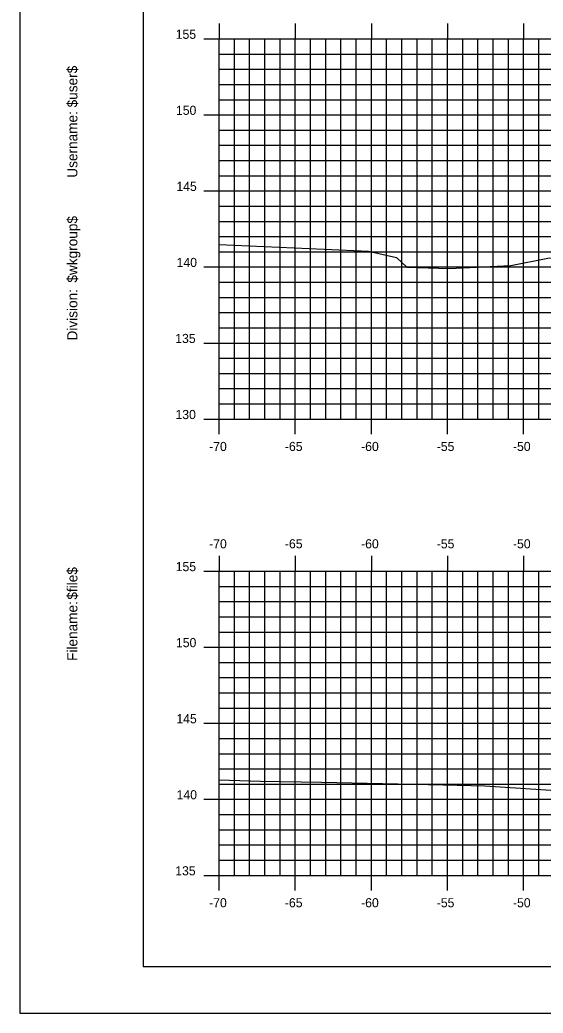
# Model space of a CAD drawing. Extents: x 851195 to 851367, y 365876 to 365986.
# Drawn here: x 851195 to 851229.4, y 365875.8 to 365941.1 of the extents above; entities that cross this region are included whole.
import ezdxf

# ---------------------------------------------------------------- set-up
doc = ezdxf.new("R2010")
doc.units = 0
for name, color, linetype in [('BORDER', 7, 'Continuous'), ('H_V ANNOTATION', 7, 'Continuous'), ('MAJOR', 7, 'Continuous'), ('MINOR', 7, 'Continuous'), ('PLOT BOUNDARY', 7, 'Continuous'), ('S_Roadway_Centerline', 7, 'Continuous')]:
    doc.layers.add(name, color=color, linetype=linetype)

msp = doc.modelspace()

# ---------------------------------------------------------------- linework, layer by layer
at = {"layer": 'BORDER'}
msp.add_lwpolyline([(851203.142, 365878.833), (851363.142, 365878.833), (851363.142, 365983.833), (851203.142, 365983.833)], close=True, dxfattribs=at)
at = {"layer": 'MAJOR'}
for p, q in [((851208.142, 365940.835), (851208.142, 365939.833)), ((851213.142, 365940.835), (851213.142, 365939.833)), ((851218.142, 365940.835), (851218.142, 365939.833)), ((851223.142, 365940.835), (851223.142, 365939.833)), ((851228.142, 365940.835), (851228.142, 365939.833)), ((851207.14, 365939.833), (851208.142, 365939.833)), ((851208.142, 365939.833), (851348.142, 365939.833)), ((851208.142, 365914.833), (851208.142, 365939.833)), ((851208.142, 365914.833), (851208.142, 365939.833)), ((851208.142, 365939.833), (851348.142, 365939.833)), ((851213.142, 365914.833), (851213.142, 365939.833)), ((851218.142, 365914.833), (851218.142, 365939.833)), ((851223.142, 365914.833), (851223.142, 365939.833)), ((851228.142, 365914.833), (851228.142, 365939.833)), ((851207.14, 365934.833), (851208.142, 365934.833)), ((851208.142, 365934.833), (851348.142, 365934.833)), ((851207.14, 365929.833), (851208.142, 365929.833)), ((851208.142, 365929.833), (851348.142, 365929.833)), ((851207.14, 365924.833), (851208.142, 365924.833)), ((851208.142, 365924.833), (851348.142, 365924.833)), ((851207.14, 365919.833), (851208.142, 365919.833)), ((851208.142, 365919.833), (851348.142, 365919.833)), ((851207.14, 365914.833), (851208.142, 365914.833)), ((851208.142, 365914.833), (851348.142, 365914.833)), ((851208.142, 365914.833), (851348.142, 365914.833)), ((851208.142, 365913.831), (851208.142, 365914.833)), ((851213.142, 365913.831), (851213.142, 365914.833)), ((851218.142, 365913.831), (851218.142, 365914.833)), ((851223.142, 365913.831), (851223.142, 365914.833)), ((851228.142, 365913.831), (851228.142, 365914.833)), ((851208.142, 365905.835), (851208.142, 365904.833)), ((851213.142, 365905.835), (851213.142, 365904.833)), ((851218.142, 365905.835), (851218.142, 365904.833)), ((851223.142, 365905.835), (851223.142, 365904.833)), ((851228.142, 365905.835), (851228.142, 365904.833)), ((851207.14, 365904.833), (851208.142, 365904.833)), ((851208.142, 365904.833), (851348.142, 365904.833)), ((851208.142, 365884.833), (851208.142, 365904.833)), ((851208.142, 365884.833), (851208.142, 365904.833)), ((851208.142, 365904.833), (851348.142, 365904.833)), ((851213.142, 365884.833), (851213.142, 365904.833)), ((851218.142, 365884.833), (851218.142, 365904.833)), ((851223.142, 365884.833), (851223.142, 365904.833)), ((851228.142, 365884.833), (851228.142, 365904.833)), ((851207.14, 365899.833), (851208.142, 365899.833)), ((851208.142, 365899.833), (851348.142, 365899.833)), ((851207.14, 365894.833), (851208.142, 365894.833)), ((851208.142, 365894.833), (851348.142, 365894.833)), ((851207.14, 365889.833), (851208.142, 365889.833)), ((851208.142, 365889.833), (851348.142, 365889.833)), ((851207.14, 365884.833), (851208.142, 365884.833)), ((851208.142, 365884.833), (851348.142, 365884.833)), ((851208.142, 365884.833), (851348.142, 365884.833)), ((851208.142, 365883.831), (851208.142, 365884.833)), ((851213.142, 365883.831), (851213.142, 365884.833)), ((851218.142, 365883.831), (851218.142, 365884.833)), ((851223.142, 365883.831), (851223.142, 365884.833)), ((851228.142, 365883.831), (851228.142, 365884.833))]:
    msp.add_line(p, q, dxfattribs=at)
at = {"layer": 'MINOR'}
for p, q in [((851209.142, 365914.833), (851209.142, 365939.833)), ((851210.142, 365914.833), (851210.142, 365939.833)), ((851211.142, 365914.833), (851211.142, 365939.833)), ((851212.142, 365914.833), (851212.142, 365939.833)), ((851214.142, 365914.833), (851214.142, 365939.833)), ((851215.142, 365914.833), (851215.142, 365939.833)), ((851216.142, 365914.833), (851216.142, 365939.833)), ((851217.142, 365914.833), (851217.142, 365939.833)), ((851219.142, 365914.833), (851219.142, 365939.833)), ((851220.142, 365914.833), (851220.142, 365939.833)), ((851221.142, 365914.833), (851221.142, 365939.833)), ((851222.142, 365914.833), (851222.142, 365939.833)), ((851224.142, 365914.833), (851224.142, 365939.833)), ((851225.142, 365914.833), (851225.142, 365939.833)), ((851226.142, 365914.833), (851226.142, 365939.833)), ((851227.142, 365914.833), (851227.142, 365939.833)), ((851229.142, 365914.833), (851229.142, 365939.833)), ((851208.142, 365938.833), (851348.142, 365938.833)), ((851208.142, 365938.833), (851209.144, 365938.833)), ((851208.142, 365937.833), (851348.142, 365937.833)), ((851208.142, 365937.833), (851209.144, 365937.833)), ((851208.142, 365936.833), (851348.142, 365936.833)), ((851208.142, 365936.833), (851209.144, 365936.833)), ((851208.142, 365935.833), (851348.142, 365935.833)), ((851208.142, 365935.833), (851209.144, 365935.833)), ((851208.142, 365933.833), (851348.142, 365933.833)), ((851208.142, 365933.833), (851209.144, 365933.833)), ((851208.142, 365932.833), (851348.142, 365932.833)), ((851208.142, 365932.833), (851209.144, 365932.833)), ((851208.142, 365931.833), (851348.142, 365931.833)), ((851208.142, 365931.833), (851209.144, 365931.833)), ((851208.142, 365930.833), (851348.142, 365930.833)), ((851208.142, 365930.833), (851209.144, 365930.833)), ((851208.142, 365928.833), (851348.142, 365928.833)), ((851208.142, 365928.833), (851209.144, 365928.833)), ((851208.142, 365927.833), (851348.142, 365927.833)), ((851208.142, 365927.833), (851209.144, 365927.833)), ((851208.142, 365926.833), (851348.142, 365926.833)), ((851208.142, 365926.833), (851209.144, 365926.833)), ((851208.142, 365925.833), (851348.142, 365925.833)), ((851208.142, 365925.833), (851209.144, 365925.833)), ((851208.142, 365923.833), (851348.142, 365923.833)), ((851208.142, 365923.833), (851209.144, 365923.833)), ((851208.142, 365922.833), (851348.142, 365922.833)), ((851208.142, 365922.833), (851209.144, 365922.833)), ((851208.142, 365921.833), (851348.142, 365921.833)), ((851208.142, 365921.833), (851209.144, 365921.833)), ((851208.142, 365920.833), (851348.142, 365920.833)), ((851208.142, 365920.833), (851209.144, 365920.833)), ((851208.142, 365918.833), (851348.142, 365918.833)), ((851208.142, 365918.833), (851209.144, 365918.833)), ((851208.142, 365917.833), (851348.142, 365917.833)), ((851208.142, 365917.833), (851209.144, 365917.833)), ((851208.142, 365916.833), (851348.142, 365916.833)), ((851208.142, 365916.833), (851209.144, 365916.833)), ((851208.142, 365915.833), (851348.142, 365915.833)), ((851208.142, 365915.833), (851209.144, 365915.833)), ((851209.142, 365884.833), (851209.142, 365904.833)), ((851210.142, 365884.833), (851210.142, 365904.833)), ((851211.142, 365884.833), (851211.142, 365904.833)), ((851212.142, 365884.833), (851212.142, 365904.833)), ((851214.142, 365884.833), (851214.142, 365904.833)), ((851215.142, 365884.833), (851215.142, 365904.833)), ((851216.142, 365884.833), (851216.142, 365904.833)), ((851217.142, 365884.833), (851217.142, 365904.833)), ((851219.142, 365884.833), (851219.142, 365904.833)), ((851220.142, 365884.833), (851220.142, 365904.833)), ((851221.142, 365884.833), (851221.142, 365904.833)), ((851222.142, 365884.833), (851222.142, 365904.833)), ((851224.142, 365884.833), (851224.142, 365904.833)), ((851225.142, 365884.833), (851225.142, 365904.833)), ((851226.142, 365884.833), (851226.142, 365904.833)), ((851227.142, 365884.833), (851227.142, 365904.833)), ((851229.142, 365884.833), (851229.142, 365904.833)), ((851208.142, 365903.833), (851348.142, 365903.833)), ((851208.142, 365903.833), (851209.144, 365903.833)), ((851208.142, 365902.833), (851348.142, 365902.833)), ((851208.142, 365902.833), (851209.144, 365902.833)), ((851208.142, 365901.833), (851348.142, 365901.833)), ((851208.142, 365901.833), (851209.144, 365901.833)), ((851208.142, 365900.833), (851348.142, 365900.833)), ((851208.142, 365900.833), (851209.144, 365900.833)), ((851208.142, 365898.833), (851348.142, 365898.833)), ((851208.142, 365898.833), (851209.144, 365898.833)), ((851208.142, 365897.833), (851348.142, 365897.833)), ((851208.142, 365897.833), (851209.144, 365897.833)), ((851208.142, 365896.833), (851348.142, 365896.833)), ((851208.142, 365896.833), (851209.144, 365896.833)), ((851208.142, 365895.833), (851348.142, 365895.833)), ((851208.142, 365895.833), (851209.144, 365895.833)), ((851208.142, 365893.833), (851348.142, 365893.833)), ((851208.142, 365893.833), (851209.144, 365893.833)), ((851208.142, 365892.833), (851348.142, 365892.833)), ((851208.142, 365892.833), (851209.144, 365892.833)), ((851208.142, 365891.833), (851348.142, 365891.833)), ((851208.142, 365891.833), (851209.144, 365891.833)), ((851208.142, 365890.833), (851348.142, 365890.833)), ((851208.142, 365890.833), (851209.144, 365890.833)), ((851208.142, 365888.833), (851348.142, 365888.833)), ((851208.142, 365888.833), (851209.144, 365888.833)), ((851208.142, 365887.833), (851348.142, 365887.833)), ((851208.142, 365887.833), (851209.144, 365887.833)), ((851208.142, 365886.833), (851348.142, 365886.833)), ((851208.142, 365886.833), (851209.144, 365886.833)), ((851208.142, 365885.833), (851348.142, 365885.833)), ((851208.142, 365885.833), (851209.144, 365885.833))]:
    msp.add_line(p, q, dxfattribs=at)
at = {"layer": 'PLOT BOUNDARY'}
msp.add_lwpolyline([(851195.049, 365875.774), (851365.049, 365875.774), (851365.049, 365985.774), (851195.049, 365985.774)], close=True, dxfattribs=at)
at = {"layer": 'S_Roadway_Centerline'}
for points in [[(851208.142, 365926.314), (851215.041, 365926.007), (851217.958, 365925.881), (851219.79, 365925.455), (851220.465, 365924.815), (851223.262, 365924.724), (851227.308, 365924.921), (851229.726, 365925.418), (851232.295, 365925.52), (851235.754, 365925.302), (851242.416, 365925.714), (851245.078, 365925.751), (851253.803, 365925.182), (851257.459, 365925.158), (851270.86, 365925.023), (851276.825, 365924.935), (851280.32, 365925.09), (851285.065, 365924.889), (851286.257, 365924.7), (851295.049, 365925.23), (851296.011, 365925.262), (851296.222, 365925.276), (851305.027, 365925.458)], [(851208.142, 365891.121), (851210.866, 365891.029), (851214.856, 365890.97), (851222.885, 365890.78), (851225.59, 365890.713), (851230.612, 365890.393)]]:
    msp.add_lwpolyline(points, dxfattribs=at)

# ---------------------------------------------------------------- texts
at = {"layer": 'BORDER'}
for s, p in [('$user$', (851198.827, 365935.325)), ('Username:', (851198.827, 365930.701)), ('$wkgroup$', (851198.827, 365923.803)), ('Division:', (851198.827, 365919.999)), ('$file$', (851198.827, 365902.959)), ('Filename:', (851198.827, 365898.932))]:
    msp.add_text(s, height=0.6696, rotation=90, dxfattribs=at).set_placement(p)
at = {"layer": 'H_V ANNOTATION'}
for s, p in [('155', (851205.288, 365939.833)), ('150', (851205.304, 365934.833)), ('145', (851205.331, 365929.833)), ('140', (851205.347, 365924.833)), ('135', (851205.256, 365919.833)), ('130', (851205.272, 365914.833)), ('-70', (851207.483, 365912.733)), ('-65', (851212.46, 365912.733)), ('-60', (851217.468, 365912.733)), ('-55', (851222.438, 365912.733)), ('-50', (851227.446, 365912.733)), ('-70', (851207.483, 365906.333)), ('-65', (851212.46, 365906.333)), ('-60', (851217.468, 365906.333)), ('-55', (851222.438, 365906.333)), ('-50', (851227.446, 365906.333)), ('155', (851205.288, 365904.833)), ('150', (851205.304, 365899.833)), ('145', (851205.331, 365894.833)), ('140', (851205.347, 365889.833)), ('135', (851205.256, 365884.833)), ('-70', (851207.483, 365882.733)), ('-65', (851212.46, 365882.733)), ('-60', (851217.468, 365882.733)), ('-55', (851222.438, 365882.733)), ('-50', (851227.446, 365882.733))]:
    msp.add_text(s, height=0.6, dxfattribs=at).set_placement(p)
at = {"layer": 'MAJOR'}
for p in [(851208.137, 365914.833), (851208.137, 365884.833)]:
    msp.add_text('-', height=0.006, dxfattribs=at).set_placement(p)

doc.saveas('drawing.dxf')
